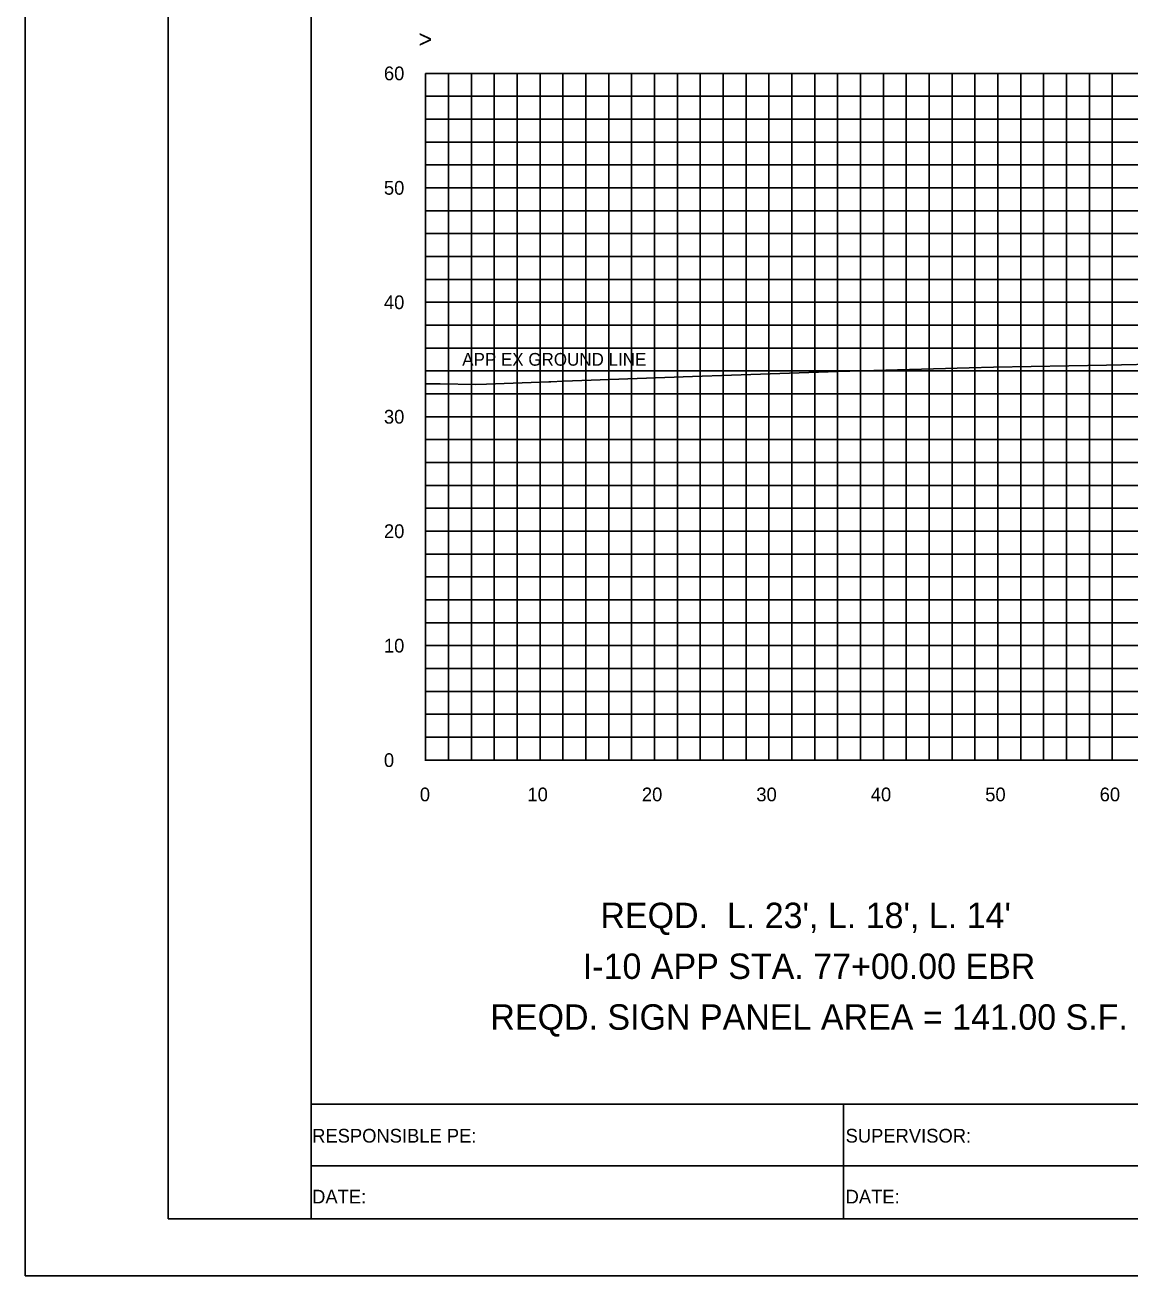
# Model space of a CAD drawing. Extents: x 2193008 to 2198143, y 1236112 to 1237864.
# Drawn here: x 2194512.7 to 2194609.2, y 1237118 to 1237227.3 of the extents above; entities that cross this region are included whole.
import ezdxf

# ---------------------------------------------------------------- set-up
doc = ezdxf.new("R2010")
doc.units = 0
for name, color, linetype in [('31', 7, 'Continuous'), ('60', 7, 'Continuous'), ('ANNO-TXT', 7, 'Continuous'), ('Level 55', 7, 'Continuous'), ('LIMT-CSLINE', 7, 'Continuous'), ('M-ROADS', 7, 'Continuous'), ('SHT-BNDRY', 7, 'Continuous')]:
    doc.layers.add(name, color=color, linetype=linetype)

msp = doc.modelspace()

# ---------------------------------------------------------------- linework, layer by layer
msp.add_lwpolyline([(2194537.69, 1237133.05), (2194837.69, 1237133.05), (2194837.69, 1237323.05), (2194537.69, 1237323.05)], close=True)
at = {"layer": '60'}
for p, q in [((2194547.69, 1237163.11), (2194547.69, 1237223.11)), ((2194547.69, 1237163.05), (2194547.69, 1237163.11)), ((2194547.69, 1237163.11), (2194677.69, 1237163.11)), ((2194557.69, 1237163.05), (2194557.69, 1237163.11)), ((2194567.69, 1237163.05), (2194567.69, 1237163.11)), ((2194577.69, 1237163.05), (2194577.69, 1237163.11)), ((2194587.69, 1237163.05), (2194587.69, 1237163.11)), ((2194597.69, 1237163.05), (2194597.69, 1237163.11)), ((2194607.69, 1237163.05), (2194607.69, 1237163.11))]:
    msp.add_line(p, q, dxfattribs=at)
at = {"layer": 'M-ROADS'}
for p, q in [((2194547.69, 1237223.11), (2194677.69, 1237223.11)), ((2194549.69, 1237163.11), (2194549.69, 1237223.11)), ((2194551.69, 1237163.11), (2194551.69, 1237223.11)), ((2194553.69, 1237163.11), (2194553.69, 1237223.11)), ((2194555.69, 1237163.11), (2194555.69, 1237223.11)), ((2194557.69, 1237163.11), (2194557.69, 1237223.11)), ((2194559.69, 1237163.11), (2194559.69, 1237223.11)), ((2194561.69, 1237163.11), (2194561.69, 1237223.11)), ((2194563.69, 1237163.11), (2194563.69, 1237223.11)), ((2194565.69, 1237163.11), (2194565.69, 1237223.11)), ((2194567.69, 1237163.11), (2194567.69, 1237223.11)), ((2194569.69, 1237163.11), (2194569.69, 1237223.11)), ((2194571.69, 1237163.11), (2194571.69, 1237223.11)), ((2194573.69, 1237163.11), (2194573.69, 1237223.11)), ((2194575.69, 1237163.11), (2194575.69, 1237223.11)), ((2194577.69, 1237163.11), (2194577.69, 1237223.11)), ((2194579.69, 1237163.11), (2194579.69, 1237223.11)), ((2194581.69, 1237163.11), (2194581.69, 1237223.11)), ((2194583.69, 1237163.11), (2194583.69, 1237223.11)), ((2194585.69, 1237163.11), (2194585.69, 1237223.11)), ((2194587.69, 1237163.11), (2194587.69, 1237223.11)), ((2194589.69, 1237163.11), (2194589.69, 1237223.11)), ((2194591.69, 1237163.11), (2194591.69, 1237223.11)), ((2194593.69, 1237163.11), (2194593.69, 1237223.11)), ((2194595.69, 1237163.11), (2194595.69, 1237223.11)), ((2194597.69, 1237163.11), (2194597.69, 1237223.11)), ((2194599.69, 1237163.11), (2194599.69, 1237223.11)), ((2194601.69, 1237163.11), (2194601.69, 1237223.11)), ((2194603.69, 1237163.11), (2194603.69, 1237223.11)), ((2194605.69, 1237163.11), (2194605.69, 1237223.11)), ((2194607.69, 1237163.11), (2194607.69, 1237223.11)), ((2194547.69, 1237221.11), (2194677.69, 1237221.11)), ((2194547.69, 1237219.11), (2194677.69, 1237219.11)), ((2194547.69, 1237217.11), (2194677.69, 1237217.11)), ((2194547.69, 1237215.11), (2194677.69, 1237215.11)), ((2194547.69, 1237213.11), (2194677.69, 1237213.11)), ((2194547.69, 1237211.11), (2194677.69, 1237211.11)), ((2194547.69, 1237209.11), (2194677.69, 1237209.11)), ((2194547.69, 1237207.11), (2194677.69, 1237207.11)), ((2194547.69, 1237205.11), (2194677.69, 1237205.11)), ((2194547.69, 1237203.11), (2194677.69, 1237203.11)), ((2194547.69, 1237201.11), (2194677.69, 1237201.11)), ((2194547.69, 1237199.11), (2194677.69, 1237199.11)), ((2194547.69, 1237197.11), (2194677.69, 1237197.11)), ((2194547.69, 1237195.11), (2194677.69, 1237195.11)), ((2194547.69, 1237193.11), (2194677.69, 1237193.11)), ((2194547.69, 1237191.11), (2194677.69, 1237191.11)), ((2194547.69, 1237189.11), (2194677.69, 1237189.11)), ((2194547.69, 1237187.11), (2194677.69, 1237187.11)), ((2194547.69, 1237185.11), (2194677.69, 1237185.11)), ((2194547.69, 1237183.11), (2194677.69, 1237183.11)), ((2194547.69, 1237181.11), (2194677.69, 1237181.11)), ((2194547.69, 1237179.11), (2194677.69, 1237179.11)), ((2194547.69, 1237177.11), (2194677.69, 1237177.11)), ((2194547.69, 1237175.11), (2194677.69, 1237175.11)), ((2194547.69, 1237173.11), (2194677.69, 1237173.11)), ((2194547.69, 1237171.11), (2194677.69, 1237171.11)), ((2194547.69, 1237169.11), (2194677.69, 1237169.11)), ((2194547.69, 1237167.11), (2194677.69, 1237167.11)), ((2194547.69, 1237165.11), (2194677.69, 1237165.11)), ((2194547.69, 1237163.11), (2194677.69, 1237163.11))]:
    msp.add_line(p, q, dxfattribs=at)
msp.add_lwpolyline([(2194512.69, 1237118.04), (2194852.69, 1237118.04), (2194852.69, 1237338.04), (2194512.69, 1237338.04)], close=True, dxfattribs=at)
msp.add_lwpolyline([(2194547.69, 1237196), (2194548.96, 1237195.98), (2194552.09, 1237195.93), (2194553.02, 1237195.96), (2194558.47, 1237196.16), (2194558.64, 1237196.17), (2194559.72, 1237196.23), (2194561.33, 1237196.29), (2194571, 1237196.64), (2194574.43, 1237196.75), (2194583.71, 1237197.05), (2194592.08, 1237197.29), (2194595.19, 1237197.39), (2194597.32, 1237197.43), (2194607.2, 1237197.62), (2194612.47, 1237197.74)], dxfattribs=at)
at = {"layer": 'SHT-BNDRY'}
for p, q in [((2194537.69, 1237123.04), (2194537.69, 1237133.05)), ((2194584.21, 1237133.05), (2194584.21, 1237123.04)), ((2194537.69, 1237127.65), (2194693.32, 1237127.65))]:
    msp.add_line(p, q, dxfattribs=at)
msp.add_lwpolyline([(2194525.19, 1237123.04), (2194847.69, 1237123.04), (2194847.69, 1237333.04), (2194525.19, 1237333.04)], close=True, dxfattribs=at)

# ---------------------------------------------------------------- texts
at = {"layer": '31'}
for s, p in [('60', (2194544.05, 1237222.51)), ('50', (2194544.05, 1237212.51)), ('40', (2194544.05, 1237202.51)), ('30', (2194544.05, 1237192.51)), ('20', (2194544.05, 1237182.51)), ('10', (2194544.05, 1237172.51)), ('0', (2194544.05, 1237162.51))]:
    msp.add_text(s, height=1.2, dxfattribs=at).set_placement(p)
at = {"layer": '60'}
msp.add_text('>', height=1.5, dxfattribs=at).set_placement((2194547.08, 1237225.36))
at = {"layer": 'ANNO-TXT'}
for s, p in [('RESPONSIBLE PE:', (2194537.78, 1237129.69)), ('SUPERVISOR:', (2194584.39, 1237129.69)), ('DATE:', (2194537.78, 1237124.37)), ('DATE:', (2194584.39, 1237124.37))]:
    msp.add_text(s, height=1.2, rotation=360, dxfattribs=at).set_placement(p)
at = {"layer": 'Level 55'}
for s, height, p in [('APP EX GROUND LINE', 1.1105, (2194550.89, 1237197.57)), (" REQD.  L. 23', L. 18', L. 14'", 2.2209, (2194562.14, 1237148.43)), ('I-10 APP STA. 77+00.00 EBR', 2.2209, (2194561.43, 1237143.99)), ('REQD. SIGN PANEL AREA = 141.00 S.F.', 2.2209, (2194553.35, 1237139.55))]:
    msp.add_text(s, height=height, dxfattribs=at).set_placement(p)
at = {"layer": 'LIMT-CSLINE'}
for s, p in [('0', (2194547.19, 1237159.51)), ('10', (2194556.59, 1237159.51)), ('20', (2194566.59, 1237159.51)), ('30', (2194576.59, 1237159.51)), ('40', (2194586.59, 1237159.51)), ('50', (2194596.59, 1237159.51)), ('60', (2194606.59, 1237159.51))]:
    msp.add_text(s, height=1.2, dxfattribs=at).set_placement(p)

doc.saveas('drawing.dxf')
